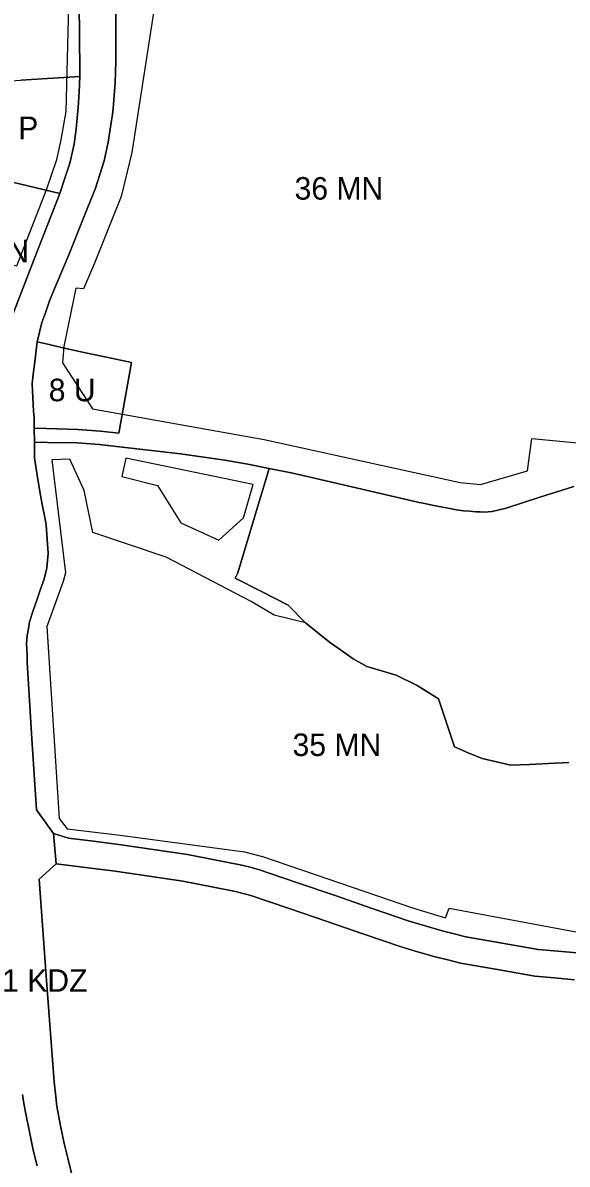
# Model space of a CAD drawing. Extents: x 7423432 to 7425824, y 5537848 to 5539677.
# Drawn here: x 7424289 to 7424531, y 5538619 to 5539125 of the extents above; entities that cross this region are included whole.
import ezdxf

# ---------------------------------------------------------------- set-up
doc = ezdxf.new("R2010")
doc.units = 0
for name, color, linetype in [('linie_rozgraniczajace', 7, 'Continuous'), ('linie_zabudowy_nieprzekraczalne', 7, 'Continuous'), ('oznaczenia_przeznaczen', 7, 'Continuous')]:
    doc.layers.add(name, color=color, linetype=linetype)

msp = doc.modelspace()

# ---------------------------------------------------------------- linework, layer by layer
at = {"layer": 'linie_rozgraniczajace'}
for points in [[(7424287.26, 5539312.04), (7424290.24, 5539292.63), (7424293.57, 5539273.07), (7424296.9, 5539253.51), (7424299.58, 5539237.59), (7424302.46, 5539219.66), (7424305.58, 5539200.31), (7424306.24, 5539196.18), (7424307.32, 5539189.77), (7424308.05, 5539185.44), (7424309.48, 5539175.58), (7424310.92, 5539165.72), (7424312.64, 5539153.65), (7424313.46, 5539147.41), (7424313.76, 5539144.58), (7424314.05, 5539141.76), (7424314.28, 5539121.55), (7424314.5, 5539101.35), (7424288.25, 5539099.74)], [(7424284.42, 5538994.92), (7424294.97, 5539022.17), (7424305.52, 5539049.42), (7424307.75, 5539056.13), (7424309.97, 5539062.85), (7424311.97, 5539071.35), (7424312.85, 5539078.08), (7424313.32, 5539082.79), (7424313.78, 5539087.5), (7424314.14, 5539094.42), (7424314.5, 5539101.35), (7424314.28, 5539121.55), (7424314.05, 5539141.76)], [(7424330.51, 5539135.48), (7424330.44, 5539121.77), (7424330.37, 5539108.05), (7424330.24, 5539103.3), (7424330.1, 5539098.55), (7424329.7, 5539092.82), (7424329.31, 5539087.1), (7424328.93, 5539084.47), (7424328.55, 5539081.85), (7424326.99, 5539072.2), (7424326.15, 5539068.06), (7424325.31, 5539063.92), (7424323.34, 5539057.82), (7424321.36, 5539051.71), (7424315.61, 5539037.35), (7424309.85, 5539022.99), (7424307.46, 5539017.36), (7424305.07, 5539011.72), (7424303.03, 5539006.73), (7424300.99, 5539001.74), (7424299.32, 5538996.93), (7424297.64, 5538992.12), (7424296.59, 5538987.87), (7424295.54, 5538983.61), (7424294.93, 5538978.59), (7424294.32, 5538973.56), (7424293.8, 5538969.24), (7424293.29, 5538964.93), (7424293.6, 5538958.82), (7424293.91, 5538952.71), (7424294.05, 5538951.42), (7424294.19, 5538950.13), (7424294.23, 5538945.31), (7424294.28, 5538939.1), (7424294.34, 5538932.1), (7424295.54, 5538924.46), (7424296.72, 5538917.08), (7424297.79, 5538911.35), (7424298.86, 5538905.63), (7424299.46, 5538902.42), (7424299.96, 5538896.01), (7424300.45, 5538889.61), (7424300.14, 5538886.45), (7424299.83, 5538883.3), (7424299.18, 5538880.76), (7424298.54, 5538878.21), (7424297.02, 5538873.78), (7424295.5, 5538869.35), (7424293.8, 5538864.36), (7424292.09, 5538859.37), (7424291.61, 5538856.4), (7424291.1, 5538853.3), (7424290.77, 5538849.8), (7424290.9, 5538846.97), (7424291.03, 5538844.14), (7424291.1, 5538841.5), (7424291.16, 5538838.85), (7424293.16, 5538807.39), (7424295.16, 5538775.92), (7424302.76, 5538765.37), (7424303.87, 5538751.91), (7424296.34, 5538745.16), (7424299.69, 5538700.12), (7424303.05, 5538655.08), (7424303.46, 5538651.16), (7424303.88, 5538647.25), (7424304.14, 5538645.35), (7424304.4, 5538643.45), (7424305.92, 5538635.64), (7424307.45, 5538627.83), (7424309.08, 5538621.23), (7424310.71, 5538614.63)], [(7424294.28, 5538939.1), (7424294.23, 5538945.31), (7424299.65, 5538945.14), (7424313.49, 5538944.67), (7424323.58, 5538943.97), (7424331.73, 5538943.05), (7424334.58, 5538958.73), (7424337.43, 5538974.42), (7424326.33, 5538976.74), (7424316.29, 5538978.9), (7424306.26, 5538981.05), (7424300.9, 5538982.33), (7424295.54, 5538983.61), (7424296.59, 5538987.87), (7424297.64, 5538992.12), (7424299.32, 5538996.93), (7424300.99, 5539001.74), (7424303.03, 5539006.73), (7424305.07, 5539011.72), (7424307.46, 5539017.36), (7424309.85, 5539022.99), (7424315.61, 5539037.35), (7424321.36, 5539051.71), (7424323.34, 5539057.82), (7424325.31, 5539063.92), (7424326.15, 5539068.06), (7424326.99, 5539072.2), (7424328.55, 5539081.85), (7424328.93, 5539084.47), (7424329.31, 5539087.1), (7424329.7, 5539092.82), (7424330.1, 5539098.55), (7424330.24, 5539103.3), (7424330.37, 5539108.05), (7424330.44, 5539121.77), (7424330.51, 5539135.48)], [(7424291.16, 5538838.85), (7424291.1, 5538841.5), (7424291.03, 5538844.14), (7424290.9, 5538846.97), (7424290.77, 5538849.8), (7424291.1, 5538853.3), (7424291.61, 5538856.4), (7424292.09, 5538859.37), (7424293.8, 5538864.36), (7424295.5, 5538869.35), (7424297.02, 5538873.78), (7424298.54, 5538878.21), (7424299.18, 5538880.76), (7424299.83, 5538883.3), (7424300.14, 5538886.45), (7424300.45, 5538889.61), (7424299.96, 5538896.01), (7424299.46, 5538902.42), (7424298.86, 5538905.63), (7424297.79, 5538911.35), (7424296.72, 5538917.08), (7424295.54, 5538924.46), (7424294.34, 5538932.1), (7424294.28, 5538939.1), (7424300.09, 5538938.96), (7424313.22, 5538938.67), (7424323.04, 5538937.99), (7424341.12, 5538935.94), (7424359.21, 5538933.88), (7424378.78, 5538931.1), (7424389.1, 5538929.31), (7424398.54, 5538927.36), (7424391.58, 5538904.22), (7424384.61, 5538881.08), (7424383.39, 5538878.71), (7424395.2, 5538872.71), (7424407.01, 5538866.7), (7424414.73, 5538858.81), (7424420.06, 5538854.57), (7424425.38, 5538850.33), (7424430.61, 5538846.6), (7424435.83, 5538842.86), (7424441.86, 5538839.49), (7424448.43, 5538837.56), (7424455, 5538835.62), (7424464.32, 5538831.09), (7424473.72, 5538825.07), (7424480.82, 5538803.83), (7424486.97, 5538801.22), (7424493.12, 5538798.62), (7424499.47, 5538797.15), (7424505.81, 5538795.67), (7424514.19, 5538796.03), (7424522.56, 5538796.39), (7424531.66, 5538796.85)], [(7424533.84, 5538919.37), (7424518.78, 5538914.58), (7424503.73, 5538909.78), (7424500.67, 5538909.01), (7424497.61, 5538908.23), (7424495.81, 5538908.08), (7424494.01, 5538907.93), (7424492.18, 5538908.05), (7424490.34, 5538908.18), (7424487.6, 5538908.38), (7424484.85, 5538908.58), (7424481.78, 5538909.05), (7424478.7, 5538909.53), (7424475.54, 5538910.16), (7424472.37, 5538910.79), (7424469.62, 5538911.36), (7424466.86, 5538911.93), (7424465.19, 5538912.3), (7424437.1, 5538918.75), (7424409.01, 5538925.21), (7424398.54, 5538927.36), (7424389.1, 5538929.31), (7424378.78, 5538931.1), (7424359.21, 5538933.88), (7424341.12, 5538935.94), (7424323.04, 5538937.99), (7424313.22, 5538938.67), (7424300.09, 5538938.96), (7424294.28, 5538939.1)], [(7424531.66, 5538796.85), (7424522.56, 5538796.39), (7424514.19, 5538796.03), (7424505.81, 5538795.67), (7424499.47, 5538797.15), (7424493.12, 5538798.62), (7424486.97, 5538801.22), (7424480.82, 5538803.83), (7424473.72, 5538825.07), (7424464.32, 5538831.09), (7424455, 5538835.62), (7424448.43, 5538837.56), (7424441.86, 5538839.49), (7424435.83, 5538842.86), (7424430.61, 5538846.6), (7424425.38, 5538850.33), (7424420.06, 5538854.57), (7424414.73, 5538858.81), (7424407.01, 5538866.7), (7424395.2, 5538872.71), (7424383.39, 5538878.71), (7424384.61, 5538881.08), (7424391.58, 5538904.22), (7424398.54, 5538927.36), (7424409.01, 5538925.21), (7424437.1, 5538918.75), (7424465.19, 5538912.3), (7424466.86, 5538911.93), (7424469.62, 5538911.36), (7424472.37, 5538910.79), (7424475.54, 5538910.16), (7424478.7, 5538909.53), (7424481.78, 5538909.05), (7424484.85, 5538908.58), (7424487.6, 5538908.38), (7424490.34, 5538908.18), (7424492.18, 5538908.05), (7424494.01, 5538907.93), (7424495.81, 5538908.08), (7424497.61, 5538908.23), (7424500.67, 5538909.01), (7424503.73, 5538909.78), (7424518.78, 5538914.58), (7424533.84, 5538919.37)], [(7424526.67, 5538713.19), (7424518.06, 5538713.95), (7424502, 5538716.76), (7424485.93, 5538719.57), (7424480.63, 5538720.88), (7424475.32, 5538722.2), (7424467.81, 5538724.41), (7424460.3, 5538726.62), (7424444.27, 5538732.14), (7424428.24, 5538737.66), (7424411.05, 5538743.52), (7424393.85, 5538749.38), (7424390.08, 5538750.36), (7424386.32, 5538751.34), (7424374.27, 5538753.71), (7424362.23, 5538756.07), (7424347.02, 5538758.3), (7424331.81, 5538760.53), (7424320.58, 5538761.92), (7424309.35, 5538763.31), (7424302.76, 5538765.37), (7424295.16, 5538775.92), (7424293.16, 5538807.39), (7424291.16, 5538838.85)], [(7424302.76, 5538765.37), (7424309.35, 5538763.31), (7424320.58, 5538761.92), (7424331.81, 5538760.53), (7424347.02, 5538758.3), (7424362.23, 5538756.07), (7424374.27, 5538753.71), (7424386.32, 5538751.34), (7424390.08, 5538750.36), (7424393.85, 5538749.38), (7424411.05, 5538743.52), (7424428.24, 5538737.66), (7424444.27, 5538732.14), (7424460.3, 5538726.62), (7424467.81, 5538724.41), (7424475.32, 5538722.2), (7424480.63, 5538720.88), (7424485.93, 5538719.57), (7424502, 5538716.76), (7424518.06, 5538713.95), (7424526.67, 5538713.19), (7424535.27, 5538712.42)], [(7424534.11, 5538700.48), (7424525.3, 5538701.26), (7424516.49, 5538702.05), (7424499.97, 5538704.93), (7424483.45, 5538707.82), (7424477.82, 5538709.22), (7424472.18, 5538710.61), (7424464.41, 5538712.9), (7424456.65, 5538715.19), (7424440.5, 5538720.75), (7424424.36, 5538726.31), (7424407.38, 5538732.09), (7424390.4, 5538737.88), (7424383.65, 5538739.64), (7424372.37, 5538741.85), (7424360.2, 5538744.24), (7424345.2, 5538746.44), (7424330.21, 5538748.64), (7424317.04, 5538750.27), (7424303.87, 5538751.91), (7424302.76, 5538765.37)], [(7424296.34, 5538745.16), (7424303.87, 5538751.91), (7424317.04, 5538750.27), (7424330.21, 5538748.64), (7424345.2, 5538746.44), (7424360.2, 5538744.24), (7424372.37, 5538741.85), (7424383.65, 5538739.64), (7424390.4, 5538737.88), (7424407.38, 5538732.09), (7424424.36, 5538726.31), (7424440.5, 5538720.75), (7424456.65, 5538715.19), (7424464.41, 5538712.9), (7424472.18, 5538710.61), (7424477.82, 5538709.22), (7424483.45, 5538707.82), (7424499.97, 5538704.93), (7424516.49, 5538702.05), (7424525.3, 5538701.26), (7424534.11, 5538700.48)], [(7424310.71, 5538614.63), (7424309.08, 5538621.23), (7424307.45, 5538627.83), (7424305.92, 5538635.64), (7424304.4, 5538643.45), (7424304.14, 5538645.35), (7424303.88, 5538647.25), (7424303.46, 5538651.16), (7424303.05, 5538655.08), (7424299.69, 5538700.12), (7424296.34, 5538745.16)], [(7424535.27, 5538712.42), (7424526.67, 5538713.19)], [(7424288.93, 5538649.59), (7424289.56, 5538645.57), (7424290.48, 5538641), (7424292.13, 5538632.91), (7424293.77, 5538624.82), (7424295.49, 5538617.86)], [(7424295.49, 5538617.86), (7424293.77, 5538624.82), (7424292.13, 5538632.91), (7424290.48, 5538641), (7424289.56, 5538645.57), (7424288.93, 5538649.59)]]:
    msp.add_lwpolyline(points, dxfattribs=at)
for points in [[(7424249.26, 5539097.11), (7424288.25, 5539099.74), (7424314.5, 5539101.35), (7424314.14, 5539094.42), (7424313.78, 5539087.5), (7424313.32, 5539082.79), (7424312.85, 5539078.08), (7424311.97, 5539071.35), (7424309.97, 5539062.85), (7424307.75, 5539056.13), (7424305.52, 5539049.42), (7424267.1, 5539058.52), (7424256.05, 5539079.02), (7424252.62, 5539085.38), (7424249.85, 5539093.32)], [(7424259.92, 5539028.68), (7424262.54, 5539047.33), (7424267.1, 5539058.52), (7424305.52, 5539049.42), (7424294.97, 5539022.17), (7424284.42, 5538994.92), (7424283.82, 5538993.42), (7424283.18, 5538991.67), (7424281.3, 5538984.77), (7424279.41, 5538977.88), (7424267.33, 5538981.83)], [(7424293.29, 5538964.93), (7424293.8, 5538969.24), (7424294.32, 5538973.56), (7424294.93, 5538978.59), (7424295.54, 5538983.61), (7424300.9, 5538982.33), (7424306.26, 5538981.05), (7424316.29, 5538978.9), (7424326.33, 5538976.74), (7424337.43, 5538974.42), (7424334.58, 5538958.73), (7424331.73, 5538943.05), (7424323.58, 5538943.97), (7424313.49, 5538944.67), (7424299.65, 5538945.14), (7424294.23, 5538945.31), (7424294.19, 5538950.13), (7424294.05, 5538951.42), (7424293.91, 5538952.71), (7424293.6, 5538958.82)]]:
    msp.add_lwpolyline(points, close=True, dxfattribs=at)
at = {"layer": 'linie_zabudowy_nieprzekraczalne'}
for points in [[(7424272.25, 5539057.3), (7424269.66, 5539046.74), (7424276.81, 5539019.63), (7424286.43, 5539017.31), (7424299.87, 5539051.45), (7424304.2, 5539064.48), (7424306.06, 5539072.43), (7424308.31, 5539085.76), (7424309.6, 5539132.87), (7424297.04, 5539218.5), (7424282.3, 5539305.84), (7424276.47, 5539305.07), (7424267.67, 5539364.7), (7424261.54, 5539410.77)], [(7424348.6, 5539139.34), (7424337.54, 5539067.6), (7424337.54, 5539067.6), (7424337.54, 5539067.6), (7424335.31, 5539058.37), (7424332.82, 5539048.05), (7424320.94, 5539018.41), (7424316.14, 5539007.11), (7424312.74, 5539007.32), (7424307.37, 5538981.45), (7424307.37, 5538981.45), (7424307.37, 5538981.45), (7424306.7, 5538974.25), (7424320.1, 5538953.77)], [(7424320.1, 5538953.77), (7424396.24, 5538940.22)], [(7424396.24, 5538940.22), (7424483.37, 5538921.07), (7424492.31, 5538920.3), (7424513.28, 5538926.25), (7424515.12, 5538940.69), (7424535.43, 5538938.68), (7424537.11, 5538950.46)], [(7424414.73, 5538858.81), (7424400.73, 5538862.2), (7424390.5, 5538868.28), (7424352.72, 5538888.07), (7424320.26, 5538899.01), (7424316.31, 5538917.61), (7424309.98, 5538931.42), (7424302.06, 5538931.26), (7424308.11, 5538881.05), (7424308.11, 5538881.05), (7424308.11, 5538881.05), (7424308.11, 5538881.05), (7424308.11, 5538881.05), (7424307.05, 5538877.26), (7424299.75, 5538857.23), (7424299.75, 5538857.23), (7424299.75, 5538857.23), (7424299.75, 5538857.23), (7424305.33, 5538772.01), (7424308.9, 5538767.41), (7424332.31, 5538764.56), (7424387.65, 5538757.19), (7424387.65, 5538757.19), (7424387.65, 5538757.19), (7424395.58, 5538755.13), (7424430.19, 5538743.34), (7424462.12, 5538732.34), (7424476.89, 5538727.99), (7424478.49, 5538732.19), (7424549.03, 5538719.03)], [(7424391.43, 5538920.3), (7424334.81, 5538931.92), (7424333.14, 5538923.81), (7424348.94, 5538919.87), (7424359.24, 5538903.18), (7424376.23, 5538895.61), (7424387.09, 5538905.41), (7424391.43, 5538920.3)]]:
    msp.add_lwpolyline(points, dxfattribs=at)

# ---------------------------------------------------------------- texts
at = {"layer": 'oznaczenia_przeznaczen'}
for s, p in [('1 P', (7424275.94, 5539073.51)), ('36 MN', (7424409.81, 5539046.68)), ('2 MN', (7424259.94, 5539018.86)), ('8 U', (7424300.65, 5538957.2)), ('35 MN', (7424408.92, 5538799.74)), ('1 KDZ', (7424279.95, 5538695.11))]:
    msp.add_text(s, height=10, dxfattribs=at).set_placement(p)

doc.saveas('drawing.dxf')
